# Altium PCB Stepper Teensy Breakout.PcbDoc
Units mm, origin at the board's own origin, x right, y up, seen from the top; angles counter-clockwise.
Board outline 195.58 x 105.66 mm, 2 copper layers (Top Layer, Bottom Layer); 48 components, 47 nets, 266 pads, 5 vias.
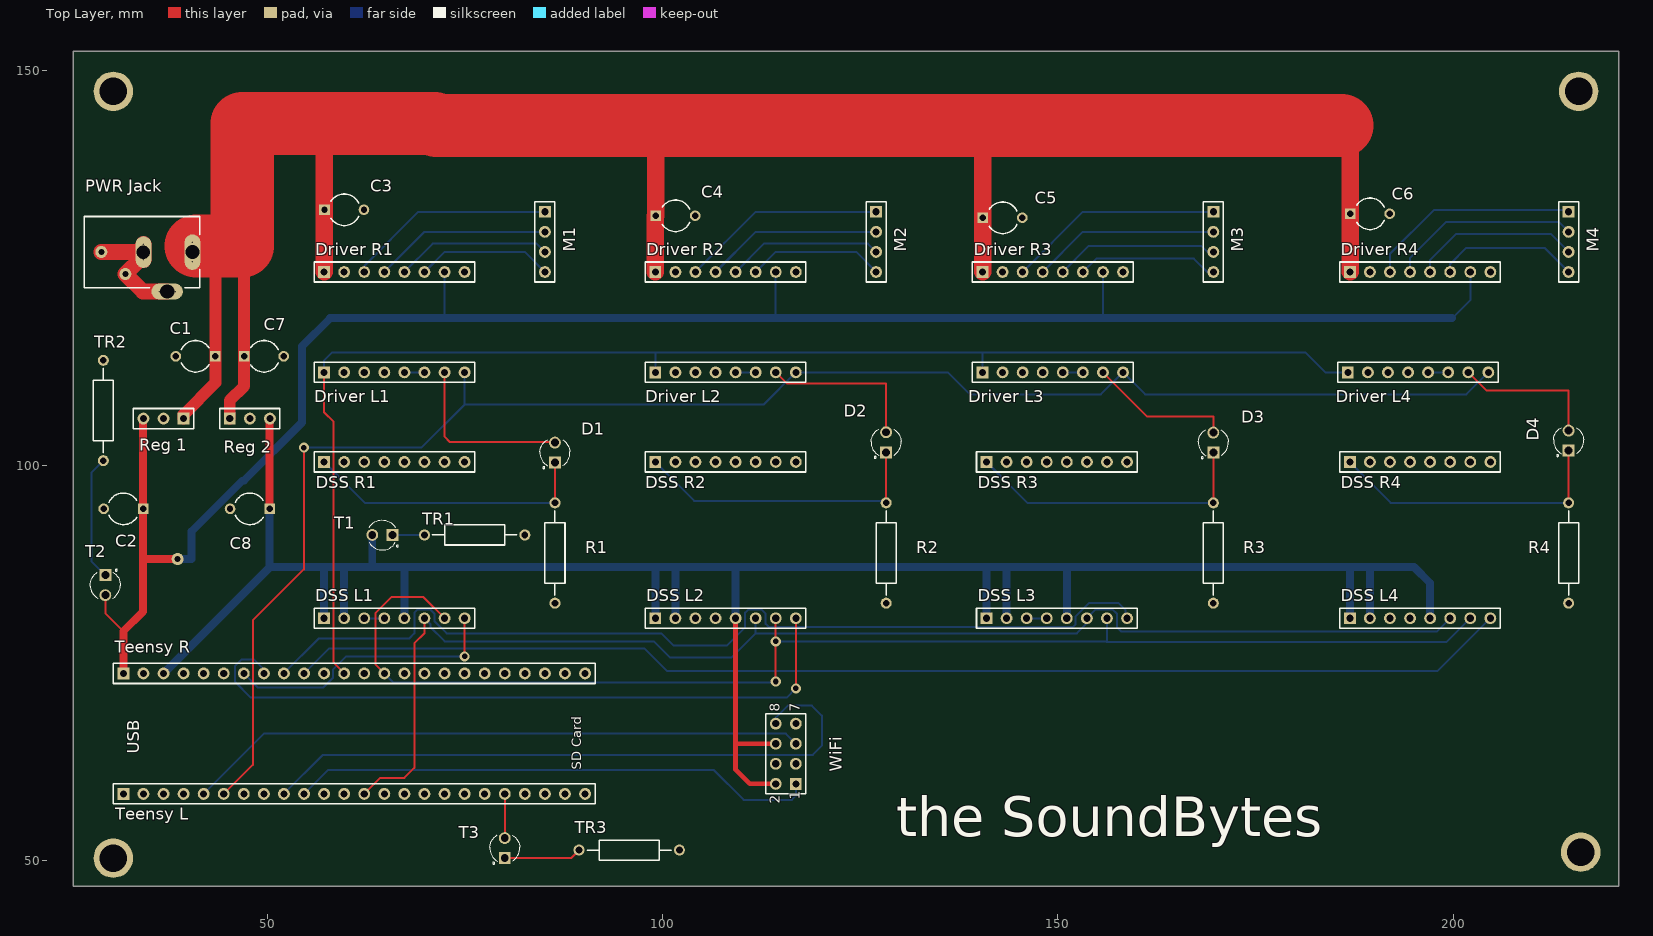
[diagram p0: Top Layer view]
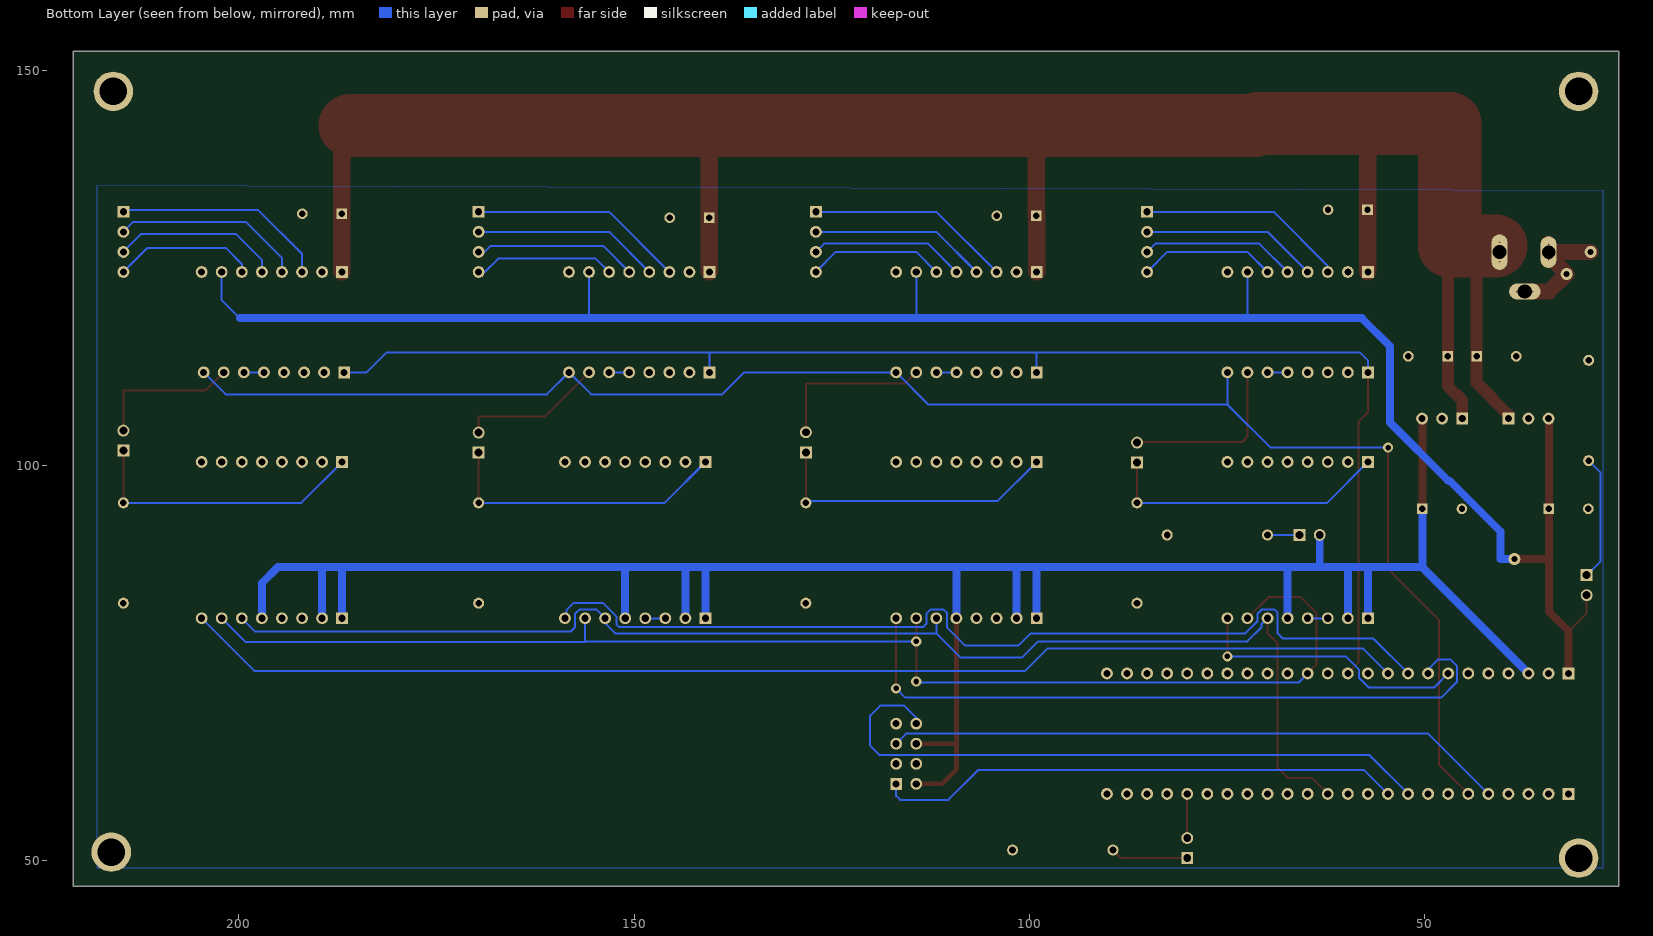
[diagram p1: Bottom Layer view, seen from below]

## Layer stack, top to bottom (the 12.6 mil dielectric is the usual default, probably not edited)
Top Solder: solder mask 0.0102, Solder Resist, Dk 3.5
Top Layer: signal copper 0.0356
Dielectric 1: dielectric 0.32, FR-4, Dk 4.8
Bottom Layer: signal copper 0.0356
Bottom Solder: solder mask 0.0102, Solder Resist, Dk 3.5

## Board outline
25.4,46.736 220.98,46.736 220.98,152.4 25.4,152.4

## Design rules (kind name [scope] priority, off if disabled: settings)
Clearance [All] p1: gap=0.254
PolygonConnect [All] p1: connectstyle=Relief reliefconductorwidth=0.254 reliefentries=4 polygonreliefangle="90 Angle" airgapwidth=0.254
RoutingVias [All] p1: holewidth=0.711 width=1.27 viastyle="Through Hole" minholewidth=0.711 minwidth=1.27 maxholewidth=0.711 maxwidth=1.27
SolderMaskExpansion [All] p1: expansion=0.102
Width Width_1 [InNet('VMOT')] p1: maxlimit=2.2 minlimit=1.5 preferedwidth=1.5 toplayer_maxwidth=1.5 minimp=50.000000 maximp=50.000000 favimp=50.000000
Width [InNet('VMOT')] p2: maxlimit=8.2 minlimit=7.6 preferedwidth=8 minimp=50.000000 maximp=50.000000 favimp=50.000000
30 further rules are at their usual default settings.

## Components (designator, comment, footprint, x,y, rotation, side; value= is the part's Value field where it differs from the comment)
C1 "Cap2" CAPR5-4X5 40.894,113.792 r180 top
C2 "Cap2" CAPR5-4X5 31.75,94.488 r180 top
C3 "" CAPR5-4X5 59.69,132.334 r0 top
C4 "Cap2" CAPR5-4X5 101.6,131.572 r0 top
C5 "Cap2" CAPR5-4X5 143.002,131.318 r0 top
C6 "Cap2" CAPR5-4X5 189.484,131.826 r0 top
C7 "Cap2" CAPR5-4X5 49.53,113.792 r0 top
C8 "Cap2" CAPR5-4X5 47.752,94.488 r180 top
D1 "LED2" LED_LTL-1CHYE_LTL-1CHYE(Primary) 86.36,101.6 r90 top
D2 "LED2" LED_LTL-1CHYE_LTL-1CHYE(Primary) 128.27,102.91 r90 top
D3 "LED2" LED_LTL-1CHYE_LTL-1CHYE(Primary) 169.672,102.87 r90 top
D4 "LED2" LED_LTL-1CHYE_LTL-1CHYE(Primary) 214.63,103.124 r90 top
"Driver L1" "Header 8" HDR1X8 57.15,111.76 r0 top locked
"Driver L2" "Header 8" HDR1X8 99.06,111.76 r0 top locked
"Driver L3" "Header 8" HDR1X8 140.462,111.76 r0 top locked
"Driver L4" "Header 8" HDR1X8 186.69,111.76 r0 top locked
"Driver R1" "Header 8" HDR1X8 57.15,124.46 r0 top locked
"Driver R2" "Header 8" HDR1X8 99.06,124.46 r0 top locked
"Driver R3" "Header 8" HDR1X8 140.462,124.46 r0 top locked
"Driver R4" "Header 8" HDR1X8 186.944,124.46 r0 top locked
"DSS L1" "Header 8" HDR1X8 57.15,80.645 r0 top locked
"DSS L2" "Header 8" HDR1X8 99.06,80.645 r0 top
"DSS L3" "Header 8" HDR1X8 140.97,80.645 r0 top locked
"DSS L4" "Header 8" HDR1X8 186.944,80.645 r0 top
"DSS R1" "Header 8" HDR1X8 57.15,100.42 r0 top locked
"DSS R2" "Header 8" HDR1X8 99.06,100.42 r0 top
"DSS R3" "Header 8" HDR1X8 140.97,100.42 r0 top
"DSS R4" "Header 8" HDR1X8 186.944,100.42 r0 top
M1 "Header 4" HDR1X4 85.09,132.08 r270 top (schematic designator "Motor 1")
M2 "Header 4" HDR1X4 127,132.08 r270 top (schematic designator "Motor 2")
M3 "Header 4" HDR1X4 169.672,132.08 r270 top (schematic designator "Motor 3")
M4 "Header 4" HDR1X4 214.63,132.08 r270 top (schematic designator "Motor 4")
"PWR Jack" "PWR2.5" KLD-0202 26.79,126.984 r0 top
R1 "Res Semi" AXIAL-0.5 86.36,88.9 r90 top
R2 "Res Semi" AXIAL-0.5 128.27,88.9 r90 top
R3 "Res Semi" AXIAL-0.5 169.672,88.9 r90 top
R4 "Res Semi" AXIAL-0.5 214.63,88.9 r90 top
"Reg 1" "Header 3" HDR1X3 39.37,105.918 r180 top (schematic designator "Sw Reg")
"Reg 2" "Header 2" HDR1X3 45.212,105.918 r0 top (schematic designator "Sw Reg1")
T1 "LTL-1CHYE" LED_LTL-1CHYE_LTL-1CHYE(Primary) 64.516,91.186 r180 top
T2 "LTL-1CHYE" LED_LTL-1CHYE_LTL-1CHYE(Primary) 29.464,84.836 r270 top
T3 "LTL-1CHYE" LED_LTL-1CHYE_LTL-1CHYE(Primary) 80.01,51.562 r90 top
"Teensy L" "Header 24" HDR1X24 31.75,58.42 r0 top locked
"Teensy R" "Header 24" HDR1X24 31.75,73.66 r0 top locked
TR1 "" AXIAL-0.5 76.2,91.186 r180 top
TR2 "" AXIAL-0.5 29.21,106.934 r270 top
TR3 "" AXIAL-0.5 95.758,51.308 r180 top
WiFi "Header 4X2" HDR2X4 116.84,59.69 r90 top (schematic designator ESP)

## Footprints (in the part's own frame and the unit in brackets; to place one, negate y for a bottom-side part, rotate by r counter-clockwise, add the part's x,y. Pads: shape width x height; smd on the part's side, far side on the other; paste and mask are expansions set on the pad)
AXIAL-0.5 [mm] "Axial Device, Thru-Hole; 2 Leads; 0.5 in Pin Spacing"
  round 1.4 hole 0.85: 1(-6.35,0) 2(6.35,0)
  silkscreen extent -5.33,-1.27 5.33,1.27
CAPR5-4X5 [mm] "Capacitor; 2 Leads"
  rect 1.35x1.35 hole 0.8: 1(-2.5,0)
  round 1.35 hole 0.8: 2(2.5,0)
  silkscreen extent -1.69,-2 1.82,2
HDR1X3 [mm] "Connector; Header; 3 Position"
  rect 1.5x1.5 hole 0.9: 1(0,0)
  round 1.5 hole 0.9: 2(2.54,0) 3(5.08,0)
  silkscreen extent -1.27,-1.27 6.35,1.27
HDR1X4 [mm] "Connector; Header; 4 Position"
  rect 1.5x1.5 hole 0.9: 1(0,0)
  round 1.5 hole 0.9: 2(2.54,0) 3(5.08,0) 4(7.62,0)
  silkscreen extent -1.27,-1.27 8.89,1.27
HDR1X8 [mm] "Connector; Header; 8 Position"
  rect 1.5x1.5 hole 0.9: 1(0,0)
  round 1.5 hole 0.9: 2(2.54,0) 3(5.08,0) 4(7.62,0) 5(10.16,0) 6(12.7,0) 7(15.24,0) 8(17.78,0)
  silkscreen extent -1.27,-1.27 19.05,1.27
HDR1X24 [mm] "Connector; Header; 24 Position"
  rect 1.5x1.5 hole 0.9: 1(0,0)
  round 1.5 hole 0.9: 2(2.54,0) 3(5.08,0) 4(7.62,0) 5(10.16,0) 6(12.7,0) 7(15.24,0) 8(17.78,0) 9(20.32,0) 10(22.86,0) 11(25.4,0) 12(27.94,0) 13(30.48,0) 14(33.02,0) 15(35.56,0) 16(38.1,0) 17(40.64,0) 18(43.18,0) 19(45.72,0) 20(48.26,0) 21(50.8,0) 22(53.34,0) 23(55.88,0) 24(58.42,0)
  silkscreen extent -1.27,-1.27 59.69,1.27
HDR2X4 [mm] "Connector; Header; 4x2 Position"
  rect 1.5x1.5 hole 0.9: 1(0,0)
  round 1.5 hole 0.9: 2(0,2.54) 3(2.54,0) 4(2.54,2.54) 5(5.08,0) 6(5.08,2.54) 7(7.62,0) 8(7.62,2.54)
  silkscreen extent -1.27,-1.27 8.89,3.81
KLD-0202 [mm] "DC Power Jack, 2.5mm, KLD Series, PCB Mount"
  oval 2x4.5 hole 1.8: 1(13.7,0)
  round 1.5 hole 0.2: 1A(13.7,-1.25) 1B(13.7,1.25) 2A(7.5,-1) 2B(7.5,1) 3A(9.5,-5) 3B(11.5,-5)
  oval 2x4 hole 1.7: 2(7.5,0)
  oval 4x2 hole 1.8: 3(10.5,-5)
  silkscreen extent 0,-4.5 14.6,4.5
LED_LTL-1CHYE_LTL-1CHYE(Primary) [mm]
  round 1.508 hole 1: A(1.27,0)
  rect 1.508x1.508 hole 1: C(-1.27,0)
  silkscreen extent -2.03,-1.9 1.66,1.9

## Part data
C1 C2 C4 C5 C6 C7 C8: "Capacitor"
C3: library part Cap2, "Capacitor"
D1 D2 D3 D4: library part LTL-1CHYE, "Yellow 3.1 mm 45° Tinted Clear 40 mcd 2.1 V LED Through Hole"
"Driver L1" "Driver L2" "Driver L3" "Driver L4" "Driver R1" "Driver R2" "Driver R3" "Driver R4" "DSS L1" "DSS L2" "DSS L3" "DSS L4" "DSS R1" "DSS R2" "DSS R3" "DSS R4": "Header, 8-Pin"
M1 M2 M3 M4: "Header, 4-Pin"
"PWR Jack": "Low Voltage Power Supply Connector"
R1 R2 R3 R4: "Semiconductor Resistor"
"Reg 1": "Header, 3-Pin"
"Reg 2": library part "Header 3", "Header, 3-Pin"
T1 T2 T3: "Yellow 3.1 mm 45° Tinted Clear 40 mcd 2.1 V LED Through Hole"
"Teensy L" "Teensy R": "Header, 24-Pin"
TR1 TR2 TR3: library part "Res Semi", "Semiconductor Resistor"
WiFi: "Header, 4-Pin, Dual row"

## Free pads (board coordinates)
  round 5 hole 3.5: 0(30.48,147.32) 6(215.9,147.32) 7(216.154,51.054) 8(30.48,50.292)
  round 1.524 hole 0.762: 2(28.956,127) 3(32.004,124.206) 5(38.608,88.138)

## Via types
v1: diameter 1.27, hole 0.711, Top Layer to Bottom Layer, 5 vias

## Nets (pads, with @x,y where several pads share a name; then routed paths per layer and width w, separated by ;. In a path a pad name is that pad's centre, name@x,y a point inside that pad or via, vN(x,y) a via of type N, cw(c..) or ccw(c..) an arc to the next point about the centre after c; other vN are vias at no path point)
1A_A: "Driver R1.5" M1.3 | length 19.7
  Bottom Layer w0.254: 67.31,124.46 70.891,128.041 84.049,128.041 M1.3
1A_B: "Driver R2.5" M2.3 | length 19.7
  Bottom Layer w0.254: 109.22,124.46 112.801,128.041 125.959,128.041 M2.3
1A_C: "Driver R3.5" M3.3 | length 20.7
  Bottom Layer w0.254: 150.622,124.46 153.924,127.762 168.148,127.762 168.91,127 M3.3
1A_D: "Driver R4.5" M4.3 | length 21.4
  Bottom Layer w0.254: 197.104,124.46 197.104,125.984 200.406,129.286 212.344,129.286 M4.3
1B_A: "Driver R1.6" M1.4 | length 17.3
  Bottom Layer w0.254: 69.85,124.46 72.39,127 82.55,127 M1.4
1B_B: "Driver R2.6" M2.4 | length 17.3
  Bottom Layer w0.254: 111.76,124.46 114.3,127 124.46,127 M2.4
1B_C: "Driver R3.6" M3.4 | length 17.9
  Bottom Layer w0.254: 153.162,124.46 154.864,126.162 167.208,126.162 168.91,124.46 M3.4
1B_D: "Driver R4.6" M4.4 | length 18.1
  Bottom Layer w0.254: 199.644,124.46 199.644,125.476 201.676,127.508 211.582,127.508 M4.4
2A_A: "Driver R1.4" M1.2 | length 22.4
  Bottom Layer w0.254: 64.77,124.46 69.85,129.54 M1.2
2A_B: "Driver R2.4" M2.2 | length 22.4
  Bottom Layer w0.254: 106.68,124.46 111.76,129.54 M2.2
2A_C: "Driver R3.4" M3.2 | length 23.7
  Bottom Layer w0.254: 148.082,124.46 153.162,129.54 M3.2
2A_D: "Driver R4.4" M4.2 | length 24.3
  Bottom Layer w0.254: 194.564,124.46 194.564,126.238 199.136,130.81 213.36,130.81 M4.2
2B_A: "Driver R1.3" M1.1 | length 26.5
  Bottom Layer w0.254: 62.23,124.46 62.23,125.222 69.088,132.08 M1.1
2B_B: "Driver R2.3" M2.1 | length 26
  Bottom Layer w0.254: 104.14,124.46 111.76,132.08 M2.1
2B_C: "Driver R3.3" M3.1 | length 27.3
  Bottom Layer w0.254: 145.542,124.46 153.162,132.08 M3.1
2B_D: "Driver R4.3" M4.1 | length 27.3
  Bottom Layer w0.254: 192.024,124.46 192.024,126.746 197.612,132.334 214.376,132.334 M4.1
3V3: "DSS L1.1" "DSS L1.2" "DSS L1.5" "DSS L2.1" "DSS L2.2" "DSS L2.5" "DSS L3.1" "DSS L3.2" "DSS L3.5" "DSS L4.1" "DSS L4.2" "DSS L4.5" "Reg 2.3" "Teensy R.3" C8.1 T1.A WiFi.2 WiFi.6 | length 295.4
  Top Layer w0.6: 109.22,80.645 109.22,64.77 ; WiFi.2 110.998,59.69 109.22,61.468 109.22,64.77 ; WiFi.6 109.22,64.77
  Top Layer w1: C8.1 50.252,105.878 50.292,105.918
  Bottom Layer w1: 36.83,73.66 50.252,87.082 50.252,87.122 ; C8.1 50.252,87.122 ; 57.15,80.645 57.15,87.122 ; 59.69,80.645 59.69,87.122 ; T1.A 63.246,87.122 ; 67.31,80.645 67.31,87.122 ; 99.06,80.645 99.06,87.122 ; 101.6,80.645 101.6,87.122 ; 109.22,80.645 109.22,87.122 ; 140.97,80.645 140.97,87.122 ; 143.51,80.645 143.51,87.122 ; 151.13,80.645 151.13,87.122 ; 186.944,80.645 186.944,87.122 ; 189.484,80.645 189.484,87.122 ; 197.104,80.645 197.104,85.09 195.072,87.122 189.484,87.122 ; 50.252,87.122 57.15,87.122 ; 57.15,87.122 59.69,87.122 ; 59.69,87.122 63.246,87.122 ; 63.246,87.122 67.31,87.122 ; 67.31,87.122 99.06,87.122 ; 99.06,87.122 101.6,87.122 ; 101.6,87.122 109.22,87.122 ; 109.22,87.122 140.97,87.122 ; 140.97,87.122 143.51,87.122 ; 143.51,87.122 151.13,87.122 ; 151.13,87.122 186.944,87.122 ; 186.944,87.122 189.484,87.122
5V: "Driver R1.7" "Driver R2.7" "Driver R3.7" "Driver R4.7" "Reg 1.3" "Teensy R.1" C2.1 pad.5 T2.A | length 249.1
  Top Layer w0.254: T2.A 29.464,81.28 31.75,78.994
  Top Layer w1: 31.75,73.66 31.75,78.994 34.25,81.494 34.25,88.138 ; 34.29,105.918 34.25,105.878 C2.1 34.25,88.138 ; pad.5 34.25,88.138
  Bottom Layer w0.254: 72.39,118.618 72.39,124.46 ; 114.3,118.618 114.3,124.46 ; 155.702,118.618 155.702,124.46 ; 199.898,118.618 202.184,120.904 202.184,124.46
  Bottom Layer w1: pad.5 40.393,88.138 40.393,91.65 46.787,98.044 46.99,98.044 54.356,105.41 54.356,115.062 57.912,118.618 72.39,118.618 114.3,118.618 155.702,118.618 199.898,118.618
28: "Teensy L.20" T3.A | length 5.6
  Top Layer w0.254: T3.A 80.01,58.42
CS1: "DSS L1.8" "Teensy R.7" | length 35.7
  Top Layer w0.254: v1(74.93,75.819) 74.93,80.645
  Bottom Layer w0.254: 46.99,73.66 48.768,71.882 57.023,71.882 58.293,73.152 58.293,74.168 59.944,75.819 v1(74.93,75.819)
CS2: "DSS L2.8" "Teensy R.8" | length 88.2
  Top Layer w0.254: v1(116.84,71.78) 116.84,80.645
  Bottom Layer w0.254: 49.53,73.66 49.53,74.168 48.26,75.438 46.736,75.438 45.847,74.549 45.847,72.644 47.879,70.612 115.672,70.612 v1(116.84,71.78)
CS3: "DSS L3.8" "Teensy R.9" | length 121.8
  Bottom Layer w0.254: 52.07,73.66 56.49,78.08 67.92,78.08 68.58,78.74 68.58,81.356 69,81.776 70.548,81.776 71.12,81.204 71.12,80.264 72.644,78.74 99.822,78.74 101.346,77.216 108.153,77.216 110.439,79.502 110.439,81.356 110.859,81.776 112.458,81.776 113.03,81.204 113.03,79.934 113.45,79.514 151.892,79.514 152.261,79.883 152.261,80.887 153.924,82.55 157.702,82.55 158.535,81.717 158.535,80.86 158.75,80.645
CS4: "DSS L4.8" "Teensy R.10" | length 155.4
  Bottom Layer w0.254: 54.61,73.66 57.785,76.835 97.663,76.835 100.559,73.939 198.018,73.939 204.724,80.645
DIR: "Driver L1.8" "Driver L2.8" "Driver L3.8" "Driver L4.8" "Teensy L.6" | length 210.5
  Top Layer w0.254: 44.45,58.42 48.133,62.103 48.133,80.391 54.585,86.843 v1(54.585,102.235)
  Bottom Layer w0.254: v1(54.585,102.235) 69.469,102.235 74.93,107.696 ; 74.93,111.76 74.93,107.696 ; 204.47,111.76 201.676,108.966 161.036,108.966 158.242,111.76 155.448,108.966 138.862,108.966 136.068,111.76 116.84,111.76 112.776,107.696 74.93,107.696
ENA: "Driver L1.1" "Driver L2.1" "Driver L3.1" "Driver L4.1" "Teensy R.12" | length 176.8
  Top Layer w0.254: 57.15,111.76 57.15,106.68 58.344,105.486 58.344,75.006 59.69,73.66
  Bottom Layer w0.254: 57.15,111.76 57.15,113.284 58.166,114.3 99.06,114.3 ; 99.06,111.76 99.06,114.3 ; 140.462,111.76 140.462,114.3 ; 186.69,111.76 183.851,111.76 181.311,114.3 140.462,114.3 ; 99.06,114.3 140.462,114.3
GND: "Driver R1.2" "Driver R1.8" "Driver R2.2" "Driver R2.8" "Driver R3.2" "Driver R3.8" "Driver R4.2" "Driver R4.8" "DSS L1.3" "DSS L1.4" "DSS L2.3" "DSS L2.4" "DSS L3.3" "DSS L3.4" "DSS L4.3" "DSS L4.4" "PWR Jack.2" "PWR Jack.2A" "PWR Jack.2B" "PWR Jack.3" "PWR Jack.3A" "PWR Jack.3B" "Reg 1.2" "Reg 2.2" "Teensy L.1" "Teensy R.2" "Teensy R.15" C1.2 C2.2 C3.2 C4.2 C5.2 C6.2 C7.2 C8.2 pad.2 pad.3 R1.1 R2.1 R3.1 R4.1 TR1.1 TR2.1 TR3.1 WiFi.7 | length 21
  Top Layer w2: pad.2 33.274,127 33.29,126.984 ; 34.29,125.984 34.036,126.238 ; 34.29,127.984 34.29,126.984 34.29,126.492 34.036,126.238 ; 37.29,121.984 36.29,121.984 34.226,121.984 pad.3 34.036,126.238
  Bottom Layer w0.254: 62.23,80.645 64.77,80.645 ; 146.05,80.645 148.59,80.645 ; 189.484,124.46 189.484,124.714
NetD1_A: "Driver L1.7" D1.A | length 22.4
  Top Layer w0.254: 72.39,111.76 72.39,103.632 73.076,102.946 86.284,102.946 D1.A
NetD2_A: "Driver L2.7" D2.A | length 20.7
  Top Layer w0.254: 114.3,111.76 115.697,110.363 128.27,110.363 D2.A
NetD3_A: "Driver L3.7" D3.A | length 18.3
  Top Layer w0.254: 155.702,111.76 161.265,106.197 169.672,106.197 D3.A
NetD4_A: "Driver L4.7" D4.A | length 18.7
  Top Layer w0.254: 201.93,111.76 204.216,109.474 214.63,109.474 D4.A
NetT1_C: T1.C TR1.2 | length 4.1
  Bottom Layer w0.254: T1.C TR1.2
NetT2_C: T2.C TR2.2 | length 15.8
  Bottom Layer w0.254: TR2.2 27.686,99.06 27.686,87.884 T2.C
NetT3_C: T3.C TR3.2 | length 9.8
  Top Layer w0.254: T3.C 88.392,50.292 TR3.2
PIN3: "Teensy L.5" WiFi.5 | length 78.6
  Bottom Layer w0.254: 41.91,58.42 49.53,66.04 115.57,66.04 WiFi.5
PIN7: "Teensy L.9" WiFi.8 | length 82.2
  Bottom Layer w0.254: 52.07,58.42 57.011,63.361 118.987,63.361 120.142,64.516 120.142,68.326 118.872,69.596 115.824,69.596 114.3,68.072 WiFi.8
PIN8: "Teensy L.10" WiFi.1 | length 66.8
  Bottom Layer w0.254: 54.61,58.42 57.658,61.468 106.426,61.468 110.236,57.658 116.332,57.658 116.84,58.166 WiFi.1
RESET1: "Driver L1.5" "Driver L1.6" | length 2.5
  Bottom Layer w0.254: 67.31,111.76 69.85,111.76
RESET2: "Driver L2.5" "Driver L2.6" | length 2.5
  Bottom Layer w0.254: 109.22,111.76 111.76,111.76
RESET3: "Driver L3.5" "Driver L3.6" | length 2.5
  Bottom Layer w0.254: 150.622,111.76 153.162,111.76
RESET4: "Driver L4.5" "Driver L4.6" | length 2.5
  Bottom Layer w0.254: 196.85,111.76 199.39,111.76
SCK: "DSS L1.7" "DSS L2.7" "DSS L3.7" "DSS L4.7" "Teensy R.14" | length 169.2
  Top Layer w0.254: 64.77,73.66 63.627,74.803 63.627,81.28 65.659,83.312 69.723,83.312 72.39,80.645 ; v1(114.3,72.644) v1(114.3,77.724) 114.3,80.645
  Bottom Layer w0.254: 64.77,73.66 65.913,72.517 v1@114.173,72.517 ; v1@114.046,72.39 v1@114.173,72.517 ; v1(114.3,72.644) v1@114.173,72.517 ; v1(114.3,77.724) 156.108,77.724 156.21,77.622 ; 156.21,80.645 156.21,77.622 ; 202.184,80.645 199.161,77.622 156.21,77.622
SDA: "DSS L1.6" "DSS L2.6" "DSS L3.6" "DSS L4.6" "Teensy L.13" | length 166.9
  Top Layer w0.254: 62.23,58.42 64.262,60.452 67.31,60.452 68.58,61.722 68.58,77.47 69.85,78.74 69.85,80.645
  Bottom Layer w0.254: 69.85,80.645 70.612,79.883 70.612,79.502 72.39,77.724 98.869,77.724 100.901,75.692 108.712,75.692 111.76,78.74 ; 111.76,80.645 111.76,78.74 ; 199.644,80.645 197.993,78.994 157.988,78.994 157.48,79.502 157.48,81.204 156.908,81.776 154.801,81.776 153.67,80.645 153.67,80.01 152.4,78.74 111.76,78.74
STEP1: "DSS R1.1" D1.C R1.2 | length 36.4
  Top Layer w0.254: R1.2 D1.C
  Bottom Layer w0.254: 57.15,100.42 62.32,95.25 R1.2
STEP2: "DSS R2.1" D2.C R2.2 | length 37.7
  Top Layer w0.254: R2.2 D2.C
  Bottom Layer w0.254: 99.06,100.42 103.976,95.504 128.016,95.504 R2.2
STEP3: "DSS R3.1" D3.C R3.2 | length 37.2
  Top Layer w0.254: R3.2 D3.C
  Bottom Layer w0.254: 140.97,100.42 146.14,95.25 R3.2
STEP4: "DSS R4.1" D4.C R4.2 | length 36.4
  Top Layer w0.254: R4.2 D4.C
  Bottom Layer w0.254: 186.944,100.42 192.114,95.25 R4.2
VMOT: "Driver R1.1" "Driver R2.1" "Driver R3.1" "Driver R4.1" "PWR Jack.1" "PWR Jack.1A" "PWR Jack.1B" "Reg 1.1" "Reg 2.1" C1.1 C3.1 C4.1 C5.1 C6.1 C7.1 | length 283.9
  Top Layer w0.254: 40.49,128.234 40.962,127.762 ; 57.15,124.46 57.19,124.5 ; 57.19,143.054 57.404,143.268 ; 71.108,143.268 71.374,143.002 ; C4.1@99.06,131.532 C4.1 ; 99.06,143.002 99.1,142.962 ; 140.462,124.46 140.502,124.5 ; 140.462,143.002 140.502,142.962 ; 185.928,143.002 186.984,141.946 ; 186.944,124.46 186.984,124.5
  Top Layer w1.5: 39.37,105.918 39.37,106.426 43.394,110.45 C1.1 43.394,124.363 46.793,127.762 ; 45.212,105.918 45.212,108.204 47.03,110.022 C7.1 47.03,127.525
  Top Layer w2.2: 46.793,127.762 47.03,127.525 ; 57.19,124.5 C3.1 57.19,143.054 ; 99.06,124.46 C4.1@99.06,131.532 ; C4.1 99.1,142.962 ; 140.502,124.5 C5.1 140.502,142.962 ; 186.984,124.5 C6.1 186.984,141.946
  Top Layer w8: 40.962,127.762 46.793,127.762 46.793,143.268 57.404,143.268 71.108,143.268 ; 71.374,143.002 99.06,143.002 140.462,143.002 185.928,143.002
pads on no net: "Driver L1.2" "Driver L1.3" "Driver L1.4" "Driver L2.2" "Driver L2.3" "Driver L2.4" "Driver L3.2" "Driver L3.3" "Driver L3.4" "Driver L4.2" "Driver L4.3" "Driver L4.4" "DSS R1.2" "DSS R1.3" "DSS R1.4" "DSS R1.5" "DSS R1.6" "DSS R1.7" "DSS R1.8" "DSS R2.2" "DSS R2.3" "DSS R2.4" "DSS R2.5" "DSS R2.6" "DSS R2.7" "DSS R2.8" "DSS R3.2" "DSS R3.3" "DSS R3.4" "DSS R3.5" "DSS R3.6" "DSS R3.7" "DSS R3.8" "DSS R4.2" "DSS R4.3" "DSS R4.4" "DSS R4.5" "DSS R4.6" "DSS R4.7" "DSS R4.8" "Teensy L.2" "Teensy L.3" "Teensy L.4" "Teensy L.7" "Teensy L.8" "Teensy L.11" "Teensy L.12" "Teensy L.14" "Teensy L.15" "Teensy L.16" "Teensy L.17" "Teensy L.18" "Teensy L.19" "Teensy L.21" "Teensy L.22" "Teensy L.23" "Teensy L.24" "Teensy R.4" "Teensy R.5" "Teensy R.6" "Teensy R.11" "Teensy R.13" "Teensy R.16" "Teensy R.17" "Teensy R.18" "Teensy R.19" "Teensy R.20" "Teensy R.21" "Teensy R.22" "Teensy R.23" "Teensy R.24" WiFi.3 WiFi.4

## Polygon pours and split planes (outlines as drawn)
GND on Bottom Layer "GND" (hatched 90Degree grid 0.508 track 0.203, shelved, pour order 0): 27.432,134.784 27.432,49.022 217.932,49.022 217.932,135.441

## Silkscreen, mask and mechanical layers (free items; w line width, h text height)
Top Overlay:
  text "USB" at 33.782,63.5 h1.52 r90
  text "SD Card" at 89.662,61.468 h1.2 r90
  text "the SoundBytes" at 129.54,53.086 h5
